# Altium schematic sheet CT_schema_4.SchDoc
size 254 x 245 mm
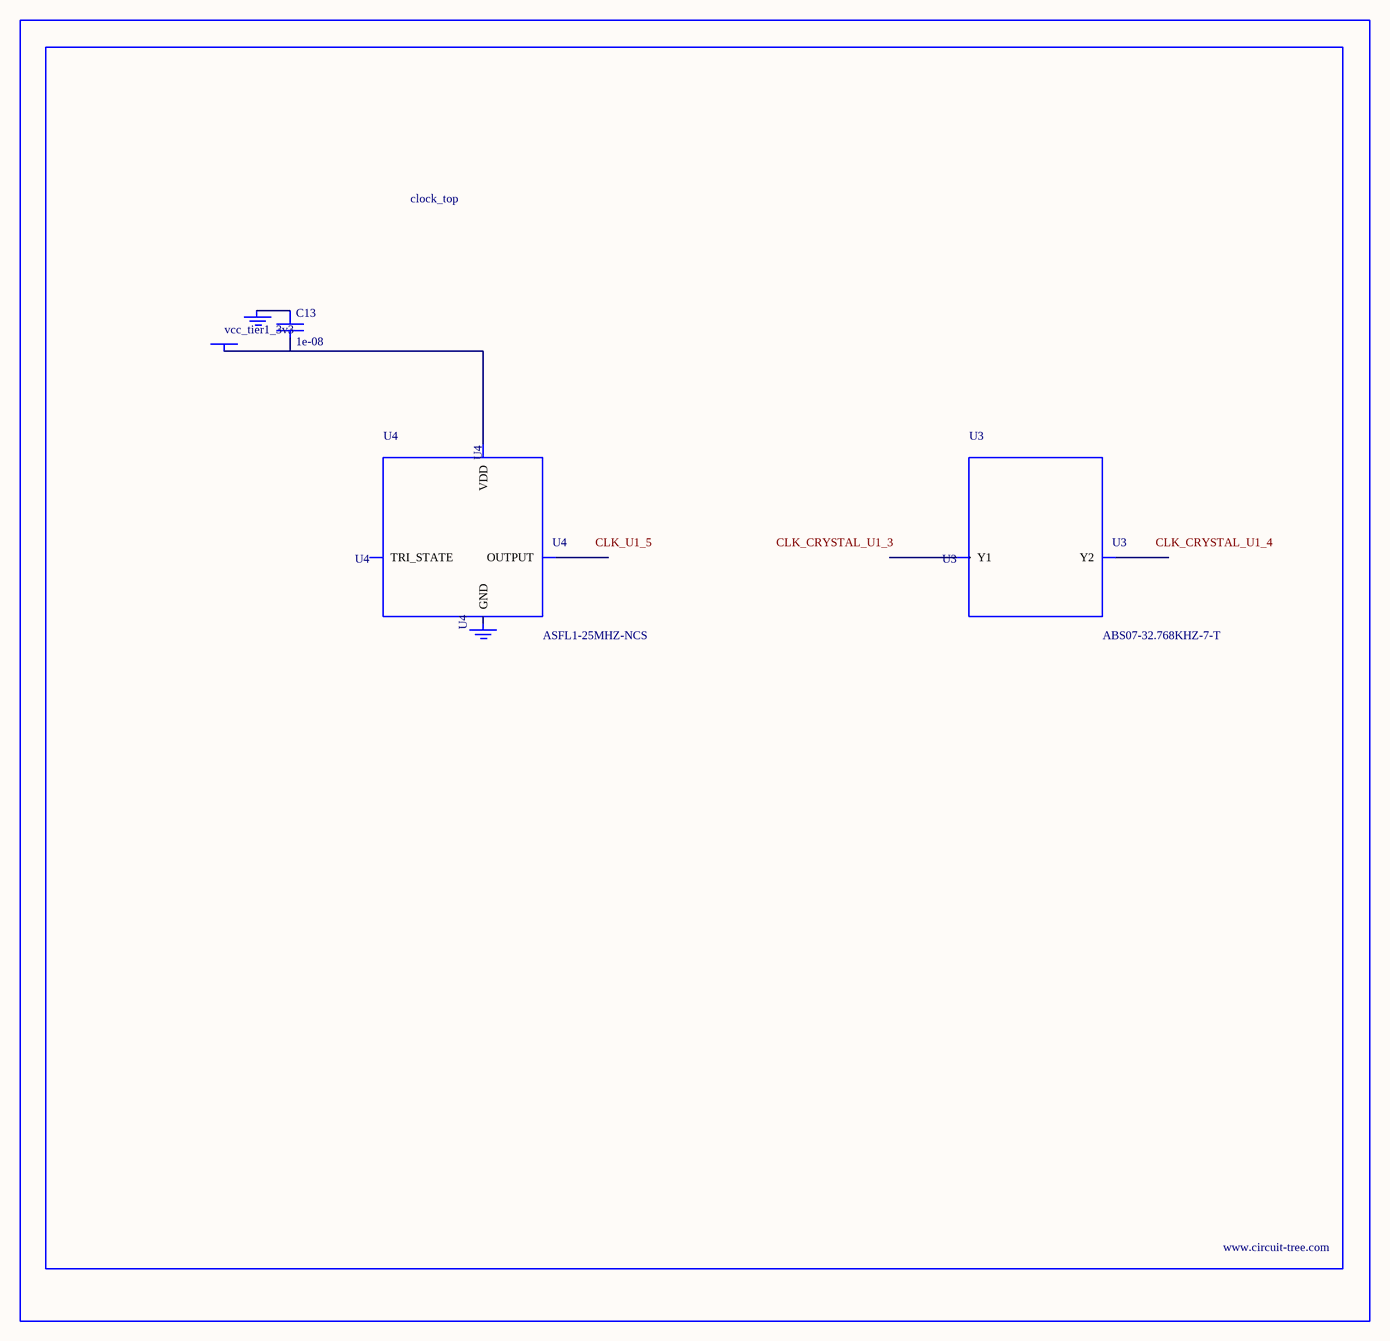
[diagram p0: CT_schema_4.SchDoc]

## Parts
BORDER3  (no value)
C13  1e-08  [C0402]
GND_INSTANCE_3_0  (no value)
GND_INSTANCE_3_1  (no value)
POWER_INSTANCE_3_0  vcc_tier1_3v3
U3  ABS07-32.768KHZ-7-T  [ABS07-32.768KHZ-7-T]
U4  ASFL1-25MHZ-NCS  [ASFL1]

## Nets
NetC13_1: C13.1 GND_INSTANCE_3_0.0(GND)
NetC13_2: C13.2 POWER_INSTANCE_3_0.0(PWR) U4.4(VDD)

Not connected (* = marked no-connect by the designer): GND_INSTANCE_3_1 0(GND); U3 1(Y1) 2(Y2); U4 1(TRI_STATE) 2(GND) 3(OUTPUT)

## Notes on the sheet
- Labels drawn without touching a wire or pin: CLK_CRYSTAL_U1_3, CLK_CRYSTAL_U1_4, CLK_U1_5

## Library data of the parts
BORDER3 = BORDER_PAGE3
C13 = C0402C103K3RAC
GND_INSTANCE_3_0 GND_INSTANCE_3_1 = GND
POWER_INSTANCE_3_0 = PWR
